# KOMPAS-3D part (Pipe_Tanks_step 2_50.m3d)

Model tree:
1. X Axis
2. Y Axis
3. Z Axis  (labels: Pipe Dn 50)
     Òîëùèíà ñòåíêè 1 = 1

Referenced files in C:\Documents and Settings\kashirsky\Мои документы\Camtasia Studio\Pipelines3D\Tanks\: Tanks_step 2.a3d
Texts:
  Pipe Dn 50
  Steel ASTM A295
  Three Point Plane
  Plane at Angle
  Line and Point Plane
  Axis through Two Vertices
  Axis of Feature
  Axis of Conical Surface
  Axis through Edge
  Trim by Surface
  Trim by Sketch
  Feature with No History
  Intersection Axis of Two Planes
  Two Line Plane
  Line and Face Plane
  Bend by line
  Hole in sheet body
  Cut in sheet body
  Point in CM
  Linear Dimension from Line to Point
  Surface Finish Symbol
  Geometric Tolerance Symbol
  Leader #1
  Leader #2
  Leader #3
  Shape Deviations and Datum
  Node point number
  Mark of coordination axis
  Node point designation
  Mark/Reference designation with leader
  Mark/reference designation on line
  Mark/Reference designation without leader
  Plane of section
